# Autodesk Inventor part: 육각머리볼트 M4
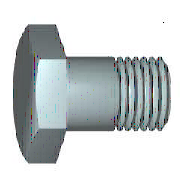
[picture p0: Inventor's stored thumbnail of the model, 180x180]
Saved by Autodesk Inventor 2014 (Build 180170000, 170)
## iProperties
IsCustomPart: 1
Created: 2012-02
Part Number: 육각머리볼트 M4
Material: 강철, 연강
Description: 6각 머리 볼트 및 6각 머리 나사
Document SubType Name: Modeling
Standard: KS B 1002
Designer: mduedu
Standards Organization: KS
Language: ko-KR
Size Designation: A + B M4 x 16
Categories: <MemberInstance><Categories><Category DisplayName="조임쇠" InternalName="e4da775c-781d-43d5-af7c-5136215cf5a6" Mnemonic="FSTN"><Category DisplayName="볼트" InternalN
Density: 7.86 g/cm^3
Appearance: Steel
Mass: 2.45486 g
Surface Area: 3.4613 cm^2
Volume: 0.312323 cm^3
Author: mduedu
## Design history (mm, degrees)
sketch "스케치1"
  geometry: L1 (0, 2.94)-(0, 2); L2 (2.1, 2)-(16, 2); L3 (16, 2)-(16, 0); L4 (16, 0)-(-0.4, 0); L5 (-3.68, 0)-(19.28, 0) reference; L6 (-0.4, 0)-(-0.4, 2.94); L7 (-0.4, 2.94)-(0, 2.94); L8 (2.1, 2)-(1.67, 2); L9 (1.67, 2)-(0, 2); L10 (0, -0.588)-(0, 3.528) reference
  constraints: 16 end point, 2 collinear, 2 perpendicular, 1 parallel
  dimensions: "d0" = 16 distance between parallel lines of L3 L1 (= NLG); "d1" = 13.9 distance from line of L2.start L3 (= GEL); "d2" = 4 diameter of L2 L4 (= GD); "d9" = 0.4001 distance between parallel lines of L6 L1 (computed from SD); "d10" = 5.88 diameter of L7 L4 (= SD2); "d13" = 0.42952 distance of L2.start L8.end (computed from GAL); "d14" = 4 diameter of L9 L4 (= BDM)
revolve "본체" sketch "스케치1" stored, may be unused: angle "d12" = 90 deg
sketch "스케치2"
  geometry: L1 (0, 4.041)-(3.5, 2.021); L2 (3.5, 2.021)-(3.5, -2.021); L3 (3.5, -2.021)-(0, -4.041); L4 (0, -4.041)-(-3.5, -2.021); L5 (-3.5, -2.021)-(-3.5, 2.021); L6 (-3.5, 2.021)-(0, 4.041); 2 further points
  constraints: 12 end point, 1 coincident, 1 vertical, 11 other
  dimensions: "d11" = 7 distance between parallel lines of L5 L2 (= SW)
extrude "머리" join sketch "스케치2" distance "d3" = 2.4 (= KOH - SD); taper "d4" = 0 deg
sketch "스케치4"
  geometry: L1 (-2.8, 3.5)-(-2.8, 4.041); L2 (-2.8, 4.041)-(-2.487, 4.041); L3 (-2.487, 4.041)-(-2.8, 3.5); L4 (-3.28, 0)-(0.08, 0) reference; L5 (-0.4, 4.041)-(-2.8, 4.041) reference; L6 (-2.8, 2.021)-(-2.8, 4.041) reference
  constraints: 6 end point, 2 collinear, 1 perpendicular, 1 vertical
  dimensions: "d5" = 30 deg angle of L3 L1 (= ANG1); "d19" = 7 diameter of L1.start L4 (= SW0)
revolve "모따기1" sketch "스케치4" stored, may be unused: angle "d21" = 90 deg
workplane "Work Plane1"
body "Solid1"
feature "스레드" dims "d15" = 13.9 (= GEL), "d16" = 0
chamfer "모따기2" distance "d6" = 0.42941 (= -0.5 x SPD + 0.5 x GD); stored, may be unused: second distance "d7" = 0.42952 (computed from GUL), angle "d55" = 45 deg
other parameters: "NLG" = 16 [user parameter; used in 1 equation term], "GD" = 4 (= NND) [user parameter; used in 2 equation terms], "BDM" = 4 (= NND) [user parameter; used in 1 equation term], "KOH" = 2.8 [user parameter; used in 1 equation term], "GEL" = 13.9 [user parameter; used in 2 equation terms], "SW" = 7 [user parameter; used in 3 equation terms], "SW0" = 7 (= SW) [user parameter; used in 1 equation term], "SPD" = 3.14117 (= NND - 1.2269 x PTC) [user parameter; used in 1 equation term], "SD2" = 5.88 (= SDH) [user parameter; used in 1 equation term], "SD" = 0.4 [user parameter; used in 2 equation terms], "ANG1" = 30 deg [user parameter; used in 1 equation term], "GAL" = 0.42941 (= 0.61345 x PTC) [user parameter; used in 1 equation term], "GUL" = 0.42941 (= 0.61345 x PTC) [user parameter; used in 1 equation term], "d8" = 0, "RR" = 0.2 [user parameter], "d57" = 0, "d58" = 0, "TPU" = 14.28571 (computed from PTC) [user parameter], "GD1" = 3.14117 (= THREADDIA - 1.2269 x PTC) [user parameter], "THREADDIA" = 4 [user parameter; used in 1 equation term], "SDH" = 5.88 [user parameter; used in 1 equation term], "SDHG" = 2.1 [user parameter], "TOA" = 30 deg [user parameter], "PTC" = 0.7 [user parameter; used in 5 equation terms], "NND" = 4 [user parameter; used in 3 equation terms], "E0" = 8.085 (= 1.155 x SW) [user parameter]
